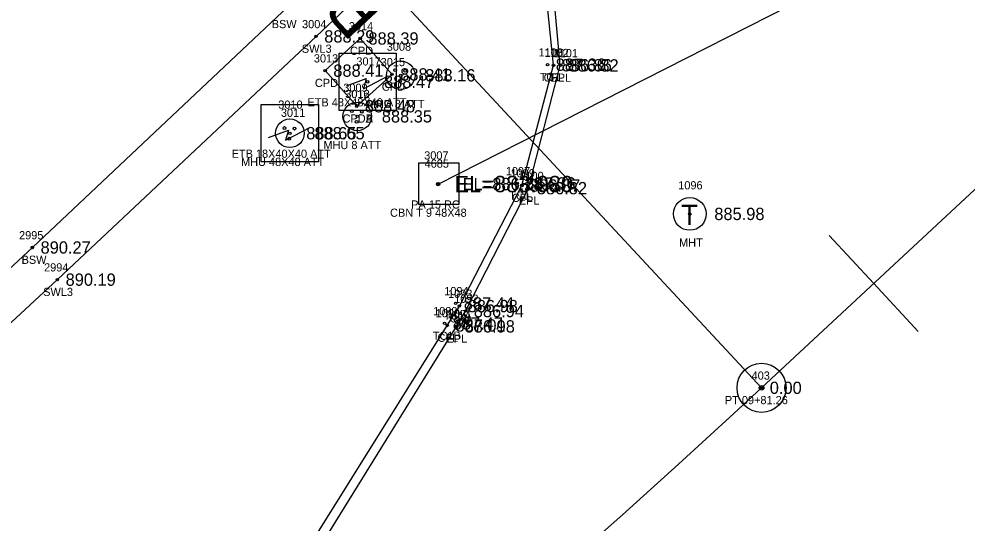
# Model space of a CAD drawing. Extents: x 1622501 to 1626664, y 1117816 to 1121579.
# Drawn here: x 1623518 to 1623634, y 1118887.8 to 1118949.4 of the extents above; entities that cross this region are included whole.
import ezdxf

# ---------------------------------------------------------------- set-up
doc = ezdxf.new("R2010")
doc.units = 0
for name, color, linetype in [('RD_EX_Conc', 7, 'Continuous'), ('RD_EX_Conc_txCode', 7, 'Continuous'), ('RD_EX_DR_Inlet', 7, 'Continuous'), ('RD_EX_DR_Inlet_txCode', 7, 'Continuous'), ('RD_EX_DR_Pipe', 7, 'Continuous'), ('RD_EX_DR_Pipe_txCode', 7, 'Continuous'), ('RD_EX_Road', 7, 'Continuous'), ('RD_EX_Road_txCode', 7, 'Continuous'), ('RD_EX_SU_Telecom', 7, 'Continuous'), ('RD_EX_TX_Conc_ELEV', 7, 'Continuous'), ('RD_EX_TX_DR_Inlet_ELEV', 7, 'Continuous'), ('RD_EX_TX_Road_ELEV', 7, 'Continuous'), ('RD_EX_TX_UT_ELEV', 7, 'Continuous'), ('RD_EX_UT', 7, 'Continuous'), ('RD_EX_UT_txCode', 7, 'Continuous'), ('RD_HC_Cl', 7, 'Continuous'), ('RD_HC_Data', 7, 'Continuous'), ('RD_HC_Data_Tic', 7, 'Continuous'), ('RD_HC_Survey_ELEV', 7, 'Continuous'), ('RD_HC_txCode', 7, 'Continuous'), ('RD_SMD_Locator', 7, 'Continuous'), ('RD_TX_Pipe_ElevEX', 7, 'Continuous')]:
    doc.layers.add(name, color=color, linetype=linetype)

msp = doc.modelspace()

# ---------------------------------------------------------------- linework, layer by layer
at = {"layer": 'RD_EX_Conc'}
for points in [[(1623552.91, 1118883.94), (1623570.41, 1118911.94), (1623571.9, 1118914.31), (1623579.53, 1118929.04), (1623583.4, 1118943.74), (1623582.1, 1118956.52), (1623576.58, 1118967.9), (1623573.88, 1118972.41), (1623568.6, 1118983.36), (1623563.87, 1119000.67), (1623564.75, 1119023.26), (1623573.58, 1119045.76)], [(1623254.61, 1118811.97), (1623256.51, 1118808.34), (1623279.85, 1118800.09), (1623320.84, 1118785.59), (1623369.89, 1118816.84), (1623408.2, 1118841.07), (1623426.14, 1118852.51), (1623428.3, 1118859.56), (1623447.17, 1118870.43), (1623479.66, 1118888.9), (1623493.5, 1118897.14), (1623519.69, 1118921.47), (1623550.27, 1118950.27), (1623567.95, 1118966.69)], [(1623278.13, 1118795.56), (1623321.56, 1118780.28), (1623372.39, 1118812.63), (1623410.78, 1118836.88), (1623430.36, 1118849.44), (1623432.31, 1118856.27), (1623449.97, 1118866.35), (1623482.09, 1118884.57), (1623496.86, 1118893.58), (1623522.75, 1118917.54), (1623554.37, 1118947.26), (1623576.13, 1118967.82)], [(1623559.34, 1118938.73), (1623555.48, 1118943.08), (1623559.77, 1118947.01), (1623563.66, 1118942.62), (1623559.34, 1118938.73)]]:
    msp.add_lwpolyline(points, dxfattribs=at)
at = {"layer": 'RD_EX_DR_Inlet'}
msp.add_line((1623571.88, 1118926.77), (1623571.88, 1118931.77), dxfattribs=at)
msp.add_lwpolyline([(1623571.88, 1118926.77), (1623571.88, 1118931.77), (1623566.88, 1118931.77), (1623566.88, 1118926.77)], close=True, dxfattribs=at)
for centre, radius in [((1623564.72, 1118942.51), 1.75), ((1623564.05, 1118943.14), 0.175), ((1623565.28, 1118943.07), 0.175), ((1623564.63, 1118941.84), 0.175), ((1623559.41, 1118937.49), 1.75), ((1623558.75, 1118938.12), 0.175), ((1623559.97, 1118938.05), 0.175), ((1623551.17, 1118935.43), 1.75), ((1623559.33, 1118936.82), 0.175), ((1623550.51, 1118936.06), 0.175), ((1623551.73, 1118935.99), 0.175), ((1623551.08, 1118934.76), 0.175)]:
    msp.add_circle(centre, radius, dxfattribs=at)
at = {"layer": 'RD_EX_DR_Pipe'}
msp.add_lwpolyline([(1623569.29, 1118929.22), (1623652.72, 1118971.59), (1623636.43, 1118995.43)], dxfattribs=at)
at = {"layer": 'RD_EX_Road'}
msp.add_lwpolyline([(1623260.54, 1118725.95), (1623288.21, 1118727.49), (1623301.48, 1118734.29), (1623344.73, 1118758.67), (1623386.19, 1118782.36), (1623428.98, 1118807.99), (1623470.08, 1118833.28), (1623514.57, 1118855.09), (1623531.48, 1118864.83), (1623546.9, 1118877), (1623552.55, 1118884.26), (1623552.91, 1118883.94), (1623553.83, 1118883.16), (1623571.54, 1118911.83), (1623572.65, 1118913.7), (1623580.36, 1118928.72), (1623584.23, 1118943.72), (1623583.03, 1118956.88), (1623577.5, 1118968.65), (1623574.75, 1118973.14), (1623569.43, 1118983.78), (1623564.78, 1119000.82), (1623565.61, 1119022.95), (1623574.2, 1119045.06)], dxfattribs=at)
at = {"layer": 'RD_EX_SU_Telecom'}
msp.add_circle((1623600.06, 1118925.57), 2, dxfattribs=at)
at = {"layer": 'RD_EX_UT'}
for points in [[(1623557.18, 1118938.21), (1623557.18, 1118945.21), (1623564.18, 1118945.21), (1623564.18, 1118938.21)], [(1623547.67, 1118931.93), (1623547.67, 1118938.93), (1623554.67, 1118938.93), (1623554.67, 1118931.93)]]:
    msp.add_lwpolyline(points, close=True, dxfattribs=at)
for points in [[(1623558.08, 1118941.21), (1623560.5, 1118942.11), (1623560.16, 1118940.86), (1623563.2, 1118942.45)], [(1623548.57, 1118934.92), (1623550.99, 1118935.82), (1623550.65, 1118934.57), (1623553.69, 1118936.17)]]:
    msp.add_lwpolyline(points, dxfattribs=at)
at = {"layer": 'RD_HC_Cl'}
msp.add_line((1623608.84, 1118904.32), (1623937.25, 1119209.79), dxfattribs=at)
msp.add_arc((1622842.02, 1119728.71), 1125.89, 297.94937, 312.92763, dxfattribs=at)
at = {"layer": 'RD_HC_Data'}
msp.add_line((1623608.84, 1118904.32), (1623532.86, 1118986), dxfattribs=at)
for radius in [3, 0.282]:
    msp.add_circle((1623608.84, 1118904.32), radius, dxfattribs=at)
at = {"layer": 'RD_HC_Data_Tic'}
for q in [(1623617.11, 1118922.94), (1623628, 1118911.22)]:
    msp.add_line((1623622.56, 1118917.08), q, dxfattribs=at)
at = {"layer": 'RD_SMD_Locator'}
for centre, radius in [((1623554.37, 1118947.26), 0.15), ((1623559.77, 1118947.01), 0.15), ((1623582.67, 1118943.81), 0.15), ((1623583.4, 1118943.74), 0.15), ((1623584.23, 1118943.72), 0.15), ((1623555.48, 1118943.08), 0.15), ((1623563.66, 1118942.62), 0.15), ((1623564.72, 1118942.51), 0.15), ((1623560.68, 1118941.71), 0.15), ((1623559.34, 1118938.73), 0.15), ((1623559.34, 1118938.73), 0.15), ((1623559.41, 1118937.49), 0.15), ((1623551.17, 1118935.43), 0.15), ((1623551.17, 1118935.43), 0.15), ((1623569.29, 1118929.22), 0.2), ((1623569.29, 1118929.22), 0.15), ((1623578.96, 1118929.3), 0.15), ((1623579.53, 1118929.04), 0.15), ((1623580.36, 1118928.72), 0.15), ((1623600.06, 1118925.57), 0.15), ((1623519.69, 1118921.47), 0.15), ((1623522.75, 1118917.54), 0.15), ((1623571.43, 1118914.64), 0.15), ((1623571.9, 1118914.31), 0.15), ((1623572.65, 1118913.7), 0.15), ((1623570.08, 1118912.19), 0.15), ((1623570.41, 1118911.94), 0.15), ((1623571.54, 1118911.83), 0.15), ((1623608.84, 1118904.32), 0.15)]:
    msp.add_circle(centre, radius, dxfattribs=at)

# ---------------------------------------------------------------- texts
at = {"layer": 'RD_EX_Conc_txCode'}
for s, p in [('BSW', (1623548.95, 1118948.27)), ('3004', (1623552.66, 1118948.26)), ('3014', (1623558.38, 1118948.01)), ('SWL3', (1623552.63, 1118945.26)), ('CPD', (1623558.52, 1118945.01)), ('1103', (1623581.57, 1118944.81)), ('3013', (1623554.1, 1118944.08)), ('1102', (1623582.3, 1118944.74)), ('3015', (1623562.27, 1118943.62)), ('TC1', (1623581.71, 1118941.81)), ('CFL', (1623582.19, 1118941.74)), ('CPD', (1623554.23, 1118941.08)), ('CPD', (1623562.41, 1118940.62)), ('3016', (1623557.93, 1118939.73)), ('3012', (1623557.95, 1118939.73)), ('CPDA', (1623557.6, 1118936.73)), ('CPDB', (1623557.61, 1118936.73)), ('1097', (1623577.57, 1118930.3)), ('1099', (1623578.14, 1118930.04)), ('TC1', (1623577.99, 1118927.3)), ('CFL', (1623578.32, 1118927.04)), ('2995', (1623518.06, 1118922.47)), ('BSW', (1623518.37, 1118919.47)), ('2994', (1623521.12, 1118918.54)), ('SWL3', (1623521.01, 1118915.54)), ('1094', (1623570.04, 1118915.64)), ('1093', (1623570.51, 1118915.31)), ('1089', (1623568.69, 1118913.19)), ('1090', (1623568.99, 1118912.94)), ('TC1A', (1623569.98, 1118912.64)), ('CFL', (1623570.69, 1118912.31)), ('TC1B', (1623568.64, 1118910.19)), ('CFL', (1623569.21, 1118909.94))]:
    msp.add_text(s, height=1, dxfattribs=at).set_placement(p)
at = {"layer": 'RD_EX_DR_Inlet_txCode'}
for s, p in [('3007', (1623567.59, 1118932.22)), ('CBN T 9 48X48', (1623563.42, 1118925.22))]:
    msp.add_text(s, height=1, dxfattribs=at).set_placement(p)
at = {"layer": 'RD_EX_DR_Pipe_txCode'}
for s, p in [('4685', (1623567.64, 1118931.22)), ('PA 15 RC', (1623566, 1118926.22))]:
    msp.add_text(s, height=1, dxfattribs=at).set_placement(p)
at = {"layer": 'RD_EX_Road_txCode'}
for s, p in [('1101', (1623583.42, 1118944.72)), ('EPL', (1623583.03, 1118941.72)), ('1100', (1623579.22, 1118929.72)), ('EPL', (1623579.16, 1118926.72)), ('1092', (1623571.26, 1118914.7)), ('1091', (1623570.43, 1118912.83)), ('EPL', (1623571.44, 1118911.7)), ('EPL', (1623570.33, 1118909.83))]:
    msp.add_text(s, height=1, dxfattribs=at).set_placement(p)
at = {"layer": 'RD_EX_SU_Telecom'}
msp.add_text('T', height=2.5, dxfattribs=at).set_placement((1623599, 1118924.2))
at = {"layer": 'RD_EX_TX_Conc_ELEV'}
for s, p in [('888.29', (1623555.37, 1118946.51)), ('888.39', (1623560.77, 1118946.26)), ('888.41', (1623556.48, 1118942.33)), ('887.36', (1623583.67, 1118943.06)), ('886.86', (1623584.4, 1118942.99)), ('888.41', (1623564.66, 1118941.87)), ('888.48', (1623560.34, 1118937.98)), ('888.48', (1623560.34, 1118937.98)), ('887.36', (1623579.96, 1118928.55)), ('886.87', (1623580.53, 1118928.29)), ('890.27', (1623520.69, 1118920.72)), ('890.19', (1623523.75, 1118916.79)), ('887.44', (1623572.43, 1118913.89)), ('886.98', (1623572.9, 1118913.56)), ('887.47', (1623571.08, 1118911.44)), ('887.01', (1623571.41, 1118911.19))]:
    msp.add_text(s, height=1.5, dxfattribs=at).set_placement(p)
at = {"layer": 'RD_EX_TX_DR_Inlet_ELEV'}
msp.add_text('EL=886.28', height=1.5, dxfattribs=at).set_placement((1623572.29, 1118928.47))
at = {"layer": 'RD_EX_TX_Road_ELEV'}
for s, p in [('886.82', (1623585.23, 1118942.97)), ('886.82', (1623581.36, 1118927.97)), ('886.94', (1623573.65, 1118912.95)), ('886.98', (1623572.54, 1118911.08))]:
    msp.add_text(s, height=1.5, dxfattribs=at).set_placement(p)
at = {"layer": 'RD_EX_TX_UT_ELEV'}
for s, p in [('888.47', (1623562.68, 1118940.96)), ('888.16', (1623567.72, 1118941.76)), ('888.35', (1623562.41, 1118936.74)), ('888.65', (1623553.17, 1118934.68)), ('888.65', (1623554.17, 1118934.68)), ('885.98', (1623603.06, 1118924.82))]:
    msp.add_text(s, height=1.5, dxfattribs=at).set_placement(p)
at = {"layer": 'RD_EX_UT_txCode'}
for s, p in [('3008', (1623563.01, 1118945.51)), ('3017', (1623559.3, 1118943.71)), ('3009', (1623557.7, 1118940.49)), ('3010', (1623549.75, 1118938.43)), ('ETB 48X48X40 ATT', (1623553.32, 1118938.71)), ('MHU 8 ATT', (1623560.58, 1118938.51)), ('3011', (1623550.07, 1118937.43)), ('MHU 8 ATT', (1623555.27, 1118933.49)), ('ETB 18X40X40 ATT', (1623544.05, 1118932.43)), ('MHU 48X48 ATT', (1623545.2, 1118931.43)), ('1096', (1623598.65, 1118928.57)), ('MHT', (1623598.75, 1118921.57))]:
    msp.add_text(s, height=1, dxfattribs=at).set_placement(p)
at = {"layer": 'RD_HC_Data'}
msp.add_text('PT=9+81.26', height=6, rotation=132.9276, dxfattribs=at).set_placement((1623563.1, 1118950.55))
at = {"layer": 'RD_HC_Survey_ELEV'}
msp.add_text('0.00', height=1.5, dxfattribs=at).set_placement((1623609.84, 1118903.57))
at = {"layer": 'RD_HC_txCode'}
for s, p in [('403', (1623607.62, 1118905.32)), ('PT 09+81.26', (1623604.35, 1118902.32))]:
    msp.add_text(s, height=1, dxfattribs=at).set_placement(p)
at = {"layer": 'RD_TX_Pipe_ElevEX'}
msp.add_text('EL=883.080', height=2, dxfattribs=at).set_placement((1623571.29, 1118928.22))

doc.saveas('drawing.dxf')
